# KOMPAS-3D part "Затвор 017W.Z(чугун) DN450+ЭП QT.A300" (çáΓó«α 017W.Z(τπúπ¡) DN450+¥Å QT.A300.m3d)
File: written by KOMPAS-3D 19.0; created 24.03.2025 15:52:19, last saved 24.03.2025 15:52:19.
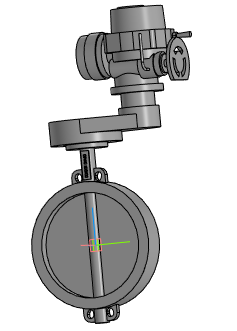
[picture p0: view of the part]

Document properties: Полное имя файла: Затвор 017W.Z(чугун) DN450+ЭП QT.A300.a3d

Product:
- Part/product: Затвор 017W.Z(чугун) DN450+ЭП QT.A300
    Масса: 337.471

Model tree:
1. Операция без истории:1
